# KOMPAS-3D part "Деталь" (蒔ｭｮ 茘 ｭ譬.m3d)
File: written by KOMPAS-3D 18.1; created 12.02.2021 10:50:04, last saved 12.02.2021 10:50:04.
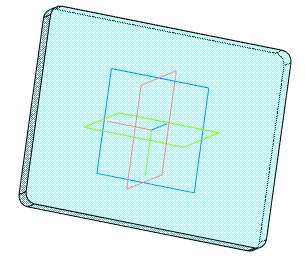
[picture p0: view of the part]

Document properties: Полное имя файла: C:\GoogleDrive\НИР\ИКИ\Компас\Окно фланца.m3d

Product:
- Part/product: Деталь
    Материал: Стекло БК10  ГОСТ 3514-94 (density 3120 kg/m3)
    Масса: 0.35501

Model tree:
1. Эскиз:1
2. Элемент выдавливания:1  (labels: Стекло БК10  ГОСТ 3514-94)
     Расстояние 1 = 10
